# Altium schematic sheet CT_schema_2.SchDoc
size 329 x 334 mm
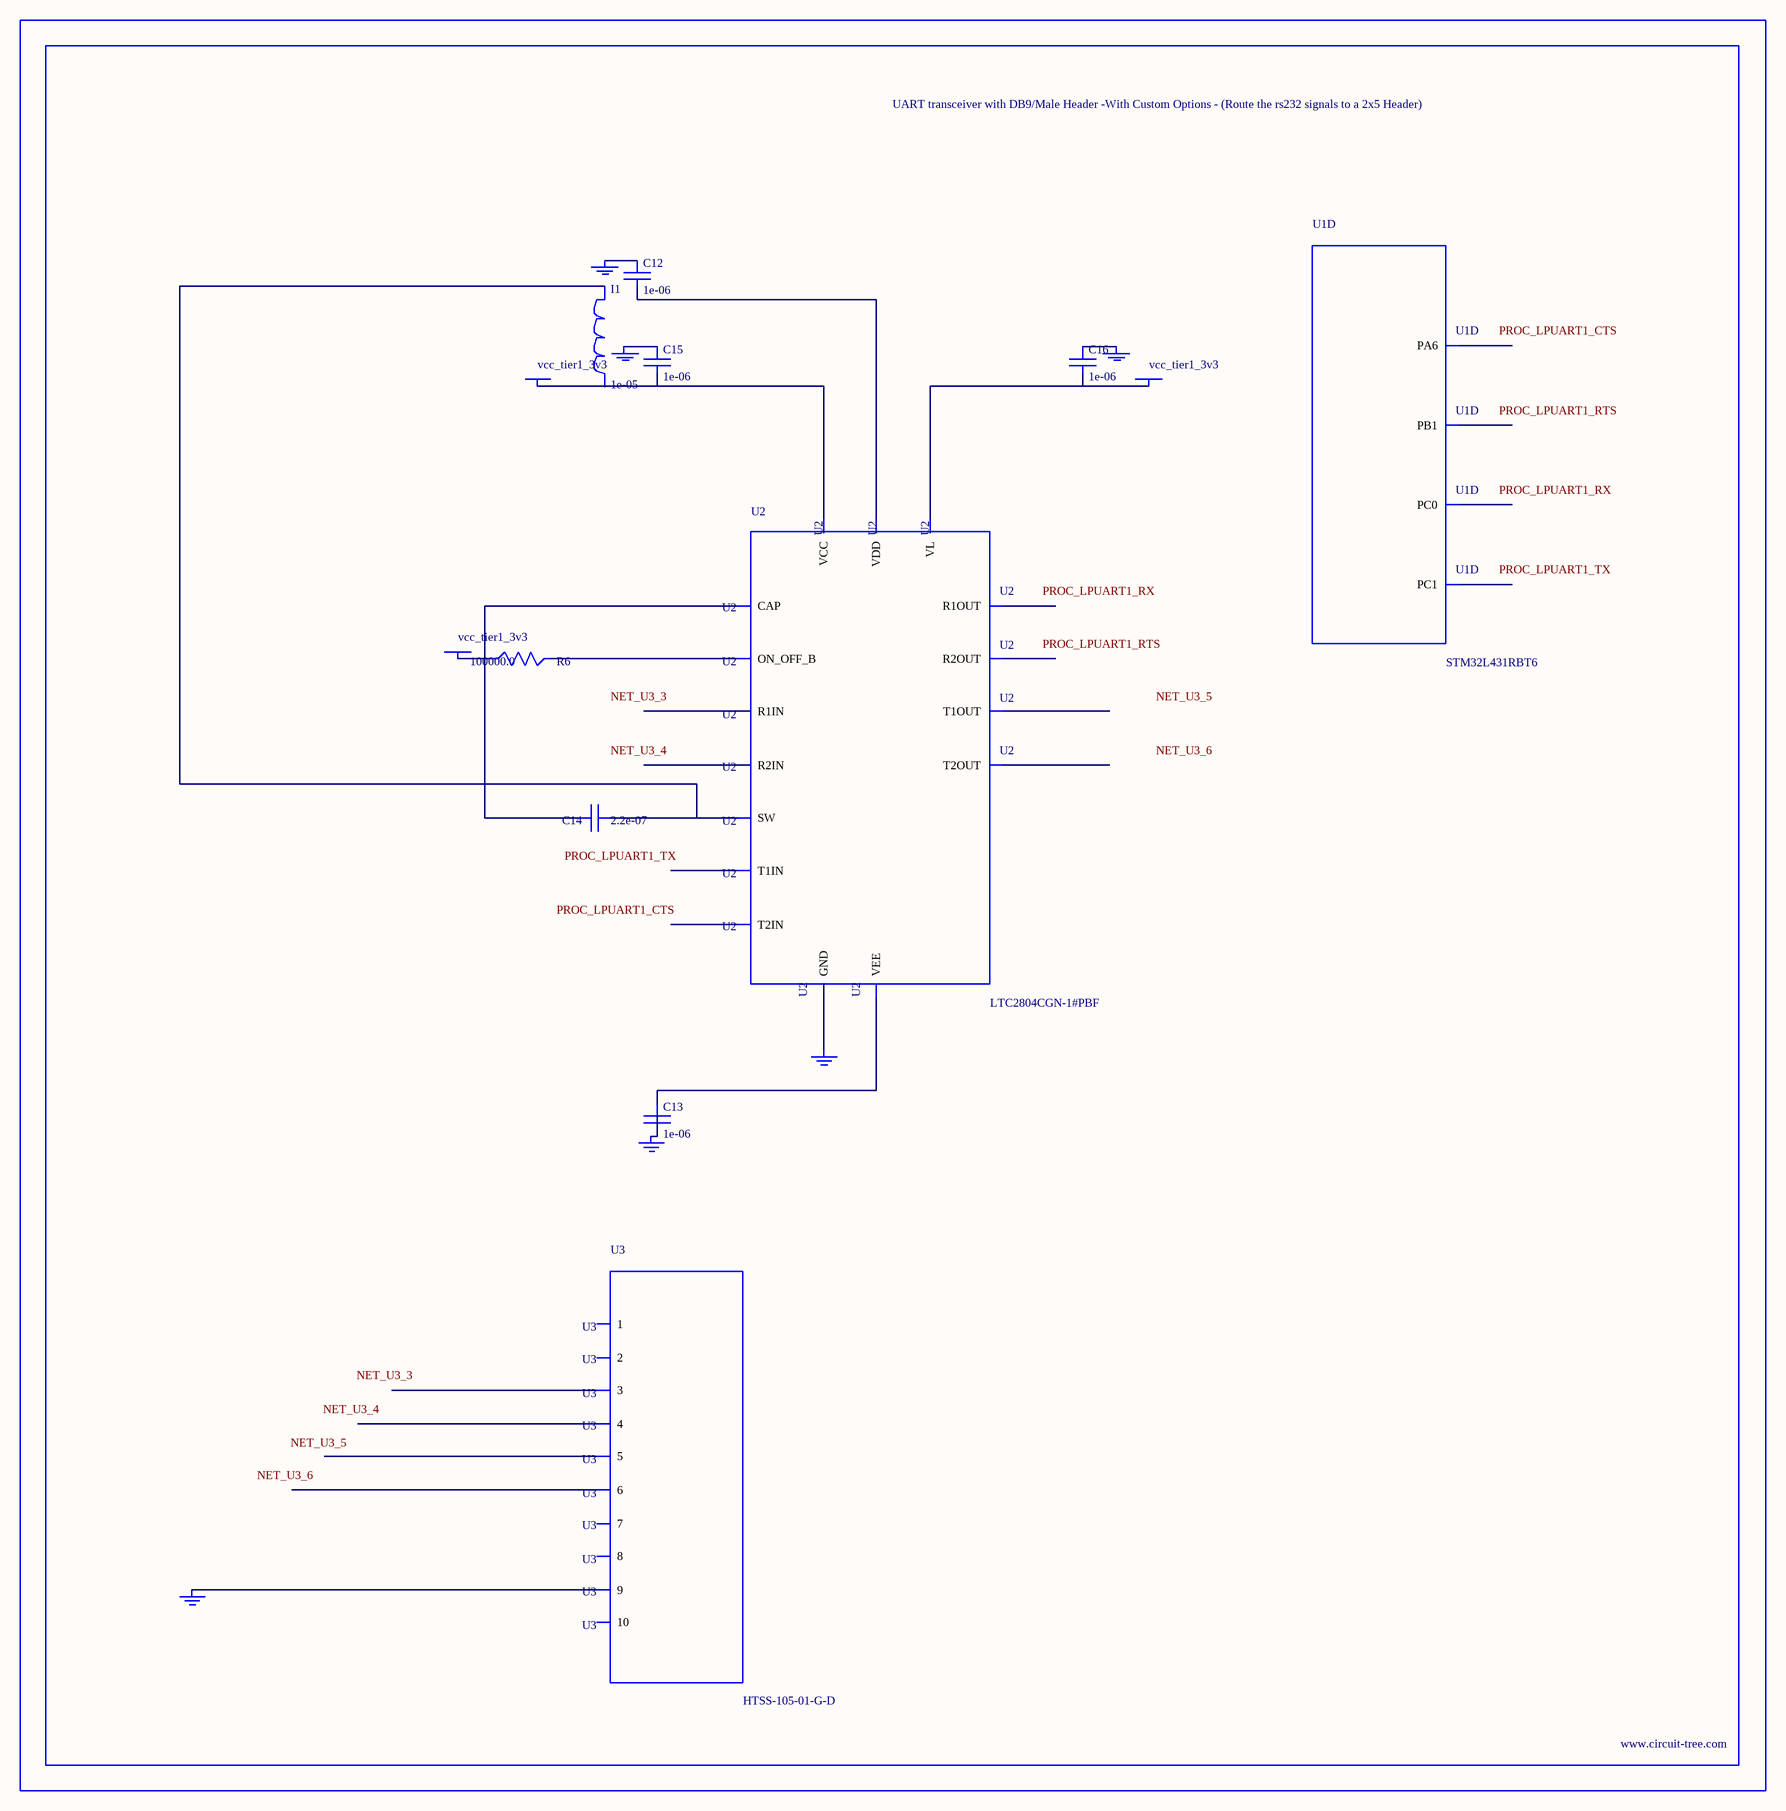
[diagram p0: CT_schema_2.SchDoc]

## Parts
BORDER1  (no value)
C12  1e-06  [C0603]
C13  1e-06  [C0603]
C14  2.2e-07  [C0603]
C15  1e-06  [C0603]
C16  1e-06  [C0603]
GND_INSTANCE_1_0  (no value)
GND_INSTANCE_1_1  (no value)
GND_INSTANCE_1_2  (no value)
GND_INSTANCE_1_3  (no value)
GND_INSTANCE_1_4  (no value)
GND_INSTANCE_1_5  (no value)
I1  1e-05  [L1210]
POWER_INSTANCE_1_0  vcc_tier1_3v3
POWER_INSTANCE_1_1  vcc_tier1_3v3
POWER_INSTANCE_1_2  vcc_tier1_3v3
R6  100000.0  [R0603]
U1  STM32L431RBT6  [LQFP64]  (part D of 7)
U2  LTC2804CGN-1#PBF  [SSOP-16]
U3  HTSS-105-01-G-D  [HTSS-105-01-G-D]

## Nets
NetC12_1: C12.1 GND_INSTANCE_1_1.0(GND)
NetC12_2: C12.2 U2.6(VDD)
NetC13_1: C13.1 U2.9(VEE)
NetC13_2: C13.2 GND_INSTANCE_1_2.0(GND)
NetC14_1: C14.1 I1.1 U2.7(SW)
NetC14_2: C14.2 U2.10(CAP)
NetC15_1: C15.1 GND_INSTANCE_1_0.0(GND)
NetC15_2: C15.2 POWER_INSTANCE_1_0.0(PWR) U2.5(VCC)
NetC16_1: C16.1 GND_INSTANCE_1_3.0(GND)
NetC16_2: C16.2 POWER_INSTANCE_1_2.0(PWR) U2.12(VL)
NetGND_INSTANCE_1_4_0: GND_INSTANCE_1_4.0(GND) U2.8(GND)
NetGND_INSTANCE_1_5_0: GND_INSTANCE_1_5.0(GND) U3.9
NetPOWER_INSTANCE_1_1_0: POWER_INSTANCE_1_1.0(PWR) R6.1
NetR6_2: R6.2 U2.11(ON_OFF_B)

Not connected (* = marked no-connect by the designer): I1 2; U1 8(PC0) 9(PC1) 22(PA6) 27(PB1); U2 1(R1IN) 2(R2IN) 3(T1OUT) 4(T2OUT) 13(T2IN) 14(T1IN) 15(R2OUT) 16(R1OUT); U3 1 2 3 4 5 6 7 8 10

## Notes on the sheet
- Labels drawn without touching a wire or pin: NET_U3_3, NET_U3_4, NET_U3_5, NET_U3_6, PROC_LPUART1_CTS, PROC_LPUART1_RTS, PROC_LPUART1_RX, PROC_LPUART1_TX

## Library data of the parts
BORDER1 = BORDER_PAGE1
C12 C13 C15 C16 = C0603C105K3RACTU
C14 = C0603C224K3RAC
GND_INSTANCE_1_0-GND_INSTANCE_1_5 = GND
I1 = CBC3225T100MR
POWER_INSTANCE_1_0-POWER_INSTANCE_1_2 = PWR
R6 = RC0603JR-07100KL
